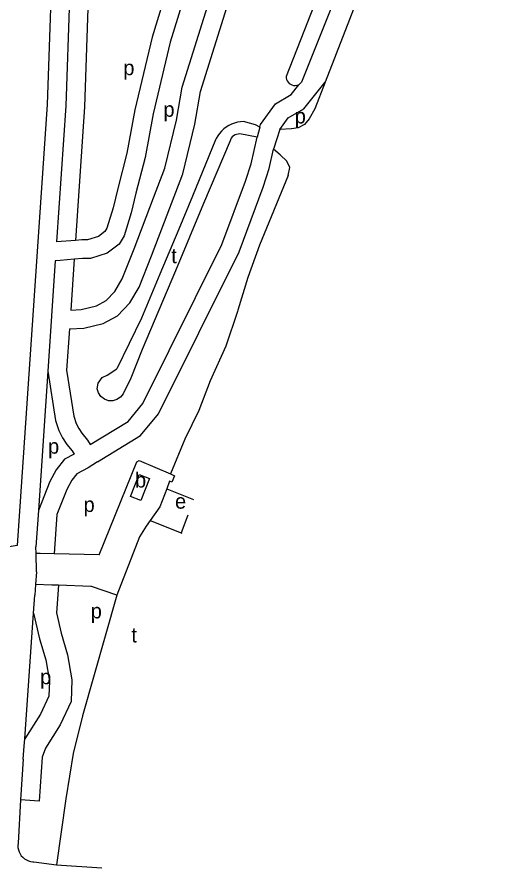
# Model space of a CAD drawing. Extents: x 157794 to 159375, y 380877 to 382306.
# Drawn here: x 159022.3 to 159149.4, y 381333.4 to 381561.1 of the extents above; entities that cross this region are included whole.
import ezdxf

# ---------------------------------------------------------------- set-up
doc = ezdxf.new("R2010")
doc.units = 0
for name, color, linetype in [('BLT_Basislijn', 7, 'Continuous'), ('BLT_Bebouwing', 7, 'Continuous'), ('BLT_Centroide', 7, 'Continuous')]:
    doc.layers.add(name, color=color, linetype=linetype)

msp = doc.modelspace()

# ---------------------------------------------------------------- linework, layer by layer
at = {"layer": 'BLT_Basislijn'}
for p, q in [((159031.37, 381565.99), (159030.38, 381537.62)), ((159036.37, 381566.07), (159035.37, 381537.28)), ((159041.37, 381566.09), (159040.37, 381537.03)), ((159097.74, 381542.91), (159098.42, 381543.64)), ((159104.74, 381543.62), (159102.01, 381536.5)), ((159030.38, 381537.62), (159022.42, 381419.62)), ((159035.37, 381537.28), (159032.92, 381500.89)), ((159040.37, 381537.03), (159037.95, 381501.27)), ((159087.26, 381531.61), (159086.59, 381528.93)), ((159092.64, 381530.94), (159090.97, 381525.68)), ((159086.59, 381528.93), (159081.96, 381529.76)), ((159079.32, 381527.95), (159072.2, 381511.17)), ((159072.2, 381511.17), (159064.69, 381493.16)), ((159065.6, 381504.32), (159060.54, 381492.28)), ((159037.95, 381501.27), (159032.92, 381500.89)), ((159039.65, 381501.4), (159037.95, 381501.27)), ((159032.58, 381495.85), (159030.58, 381466.3)), ((159033.87, 381495.95), (159032.58, 381495.85)), ((159037.61, 381496.23), (159033.87, 381495.95)), ((159037.61, 381496.23), (159036.7, 381482.64)), ((159060.54, 381492.28), (159055.66, 381480.47)), ((159064.69, 381493.16), (159055.78, 381472.1)), ((159055.66, 381480.47), (159049.01, 381466.95)), ((159036.36, 381477.61), (159035.61, 381466.52)), ((159030.58, 381466.3), (159028.07, 381429.01)), ((159063.36, 381438.8), (159064.49, 381438.32)), ((159062.37, 381434.85), (159069.53, 381431.96)), ((159028.07, 381429.01), (159027.41, 381419.28)), ((159033, 381427.91), (159032.29, 381417.41)), ((159057.92, 381426.33), (159066.24, 381423.03)), ((159068.06, 381427.76), (159066.24, 381423.03)), ((159055.07, 381421.97), (159049.06, 381406.33)), ((159066.24, 381423.03), (159066.38, 381422.97)), ((159022.42, 381419.62), (159011.92, 381417.93)), ((159027.44, 381417.53), (159027.41, 381419.28)), ((159027.54, 381412.62), (159027.44, 381417.53)), ((159028.49, 381417.51), (159027.44, 381417.53)), ((159032.29, 381417.41), (159028.49, 381417.51)), ((159044.27, 381417.12), (159032.29, 381417.41)), ((159027.54, 381412.62), (159027.31, 381409.24)), ((159027.31, 381409.24), (159027.12, 381406.39)), ((159031.63, 381409.08), (159027.31, 381409.24)), ((159033.44, 381409.01), (159031.63, 381409.08)), ((159042.06, 381408.69), (159033.44, 381409.01)), ((159026.78, 381401.55), (159027.12, 381406.39)), ((159024.4, 381367.92), (159026.78, 381401.55)), ((159024.26, 381365.96), (159024.4, 381367.92)), ((159024.01, 381362.48), (159024.26, 381365.96)), ((159024.01, 381362.48), (159023.26, 381351.59)), ((159023.26, 381351.59), (159022.6, 381339.99)), ((159026.6, 381335.02), (159026.79, 381334.99)), ((159026.79, 381334.99), (159032.89, 381334.17)), ((159032.89, 381334.17), (159045.02, 381333.37))]:
    msp.add_line(p, q, dxfattribs=at)
for points in [[(159149.36, 381672.32), (159141.87, 381652.41), (159100, 381547.62), (159098.42, 381543.64)], [(159036.36, 381477.61), (159040.23, 381477.84), (159045.36, 381479.09), (159049.18, 381481.13), (159052.52, 381484.54), (159054.98, 381488.78), (159058.34, 381497.19), (159066.67, 381519.12), (159069.91, 381532.4), (159071.39, 381541.15), (159080.3, 381569.64), (159085.12, 381578.02), (159089.78, 381584.29), (159098.44, 381594.27), (159112.17, 381608.95)], [(159127.48, 381601.4), (159114.23, 381568.04), (159104.74, 381543.62)], [(159113.39, 381593.87), (159100, 381559.65), (159094.31, 381545.18)], [(159065.13, 381575), (159062.85, 381569.99), (159058.49, 381555.65), (159053.86, 381536.2), (159051.72, 381524.58), (159049.29, 381515.13), (159048.08, 381509.99), (159046.35, 381504.53), (159045.84, 381503.67), (159044.1, 381502.37), (159041.2, 381501.4), (159039.65, 381501.4)], [(159069.55, 381572.64), (159067.54, 381568.22), (159063.32, 381554.35), (159058.76, 381535.17), (159056.61, 381523.5), (159054.14, 381513.94), (159052.9, 381508.66), (159050.95, 381502.47), (159049.62, 381500.26), (159046.46, 381497.89), (159042.01, 381496.4), (159039.86, 381496.4), (159037.61, 381496.23)], [(159036.7, 381482.64), (159039.49, 381482.81), (159043.56, 381483.8), (159046.14, 381485.18), (159048.51, 381487.6), (159050.47, 381490.97), (159053.68, 381499.01), (159058.85, 381512.64), (159061.88, 381520.61), (159065.01, 381533.42), (159066.52, 381542.32), (159069.42, 381551.61), (159072.27, 381560.74), (159075.04, 381569.57)], [(159094.31, 381545.18), (159094.32, 381544.76), (159094.42, 381544.34), (159094.59, 381543.95), (159094.83, 381543.59), (159095.13, 381543.29), (159095.48, 381543.04), (159095.87, 381542.87), (159096.29, 381542.77), (159096.72, 381542.75), (159097.14, 381542.81), (159097.74, 381542.91)], [(159087.26, 381531.61), (159087.44, 381532.26), (159091.43, 381537.86), (159095.68, 381540.36), (159097.74, 381542.91)], [(159092.64, 381530.94), (159094.89, 381534.09), (159099, 381536.52), (159104.74, 381543.62)], [(159102.01, 381536.5), (159100.44, 381533.8), (159099.21, 381532.26), (159097.53, 381531.42), (159095.76, 381531.11), (159092.64, 381530.94)], [(159082.89, 381533.11), (159082.08, 381533.05), (159081.27, 381532.91), (159080.48, 381532.69), (159079.71, 381532.4), (159078.98, 381532.03), (159078.29, 381531.59), (159077.64, 381531.09), (159077.04, 381530.53), (159076.5, 381529.91), (159076.03, 381529.24), (159075.62, 381528.53), (159075.46, 381528.19)], [(159087.26, 381531.61), (159086.14, 381532.23), (159082.89, 381533.11)], [(159041.89, 381446.64), (159052.05, 381452.87), (159055.98, 381457.63), (159077.14, 381500.17), (159083.45, 381517.16), (159084.93, 381521.81), (159086.59, 381528.93)], [(159081.96, 381529.76), (159081.51, 381529.75), (159081.06, 381529.66), (159080.64, 381529.5), (159080.25, 381529.27), (159079.92, 381528.97), (159079.63, 381528.61), (159079.42, 381528.22), (159079.32, 381527.95)], [(159075.46, 381528.19), (159069.27, 381513.08), (159065.6, 381504.32)], [(159043.89, 381442), (159055.38, 381449.04), (159060.2, 381454.89), (159081.74, 381498.18), (159088.18, 381515.52), (159089.76, 381520.48), (159090.97, 381525.68)], [(159094.84, 381518.61), (159095.3, 381520.83), (159094.46, 381522.52), (159092.69, 381524.21), (159090.97, 381525.68)], [(159094.84, 381518.61), (159087.19, 381500), (159084.1, 381491.35), (159081.38, 381482.58), (159081.29, 381482.28)], [(159081.29, 381482.28), (159078.21, 381472.96), (159074.02, 381463.74), (159070.93, 381455.77), (159067.2, 381448.08), (159063.36, 381438.8)], [(159055.78, 381472.1), (159052.78, 381464.4), (159050.74, 381460.26), (159050, 381459.32), (159049.05, 381458.68), (159047.92, 381458.36), (159046.77, 381458.4), (159045.72, 381458.77), (159044.75, 381459.52), (159044.1, 381460.49), (159043.78, 381461.61), (159044.02, 381463.08), (159045.13, 381464.61), (159046.48, 381465.26), (159049.01, 381466.95)], [(159030.58, 381466.3), (159032.62, 381453.08), (159033.54, 381450.39), (159034.48, 381448.49), (159035.62, 381446.68), (159037.1, 381444.98), (159037.58, 381444.11), (159035.05, 381442.77), (159032.78, 381439.89), (159031.09, 381436.78), (159028.07, 381429.01)], [(159035.61, 381466.52), (159037.49, 381454.28), (159038.17, 381452.31), (159038.85, 381450.94), (159039.65, 381449.67), (159041.23, 381447.85), (159041.89, 381446.64)], [(159044.27, 381417.12), (159054.39, 381442.07), (159054.96, 381442.39), (159063.36, 381438.8)], [(159043.89, 381442), (159041.36, 381440.46), (159038.32, 381438.84), (159036.97, 381437.13), (159035.64, 381434.67), (159033, 381427.91)], [(159064.49, 381438.32), (159063.77, 381436.62), (159063.13, 381436.87), (159062.37, 381434.85)], [(159062.37, 381434.85), (159060.52, 381429.98), (159057.92, 381426.33)], [(159057.92, 381426.33), (159056.86, 381424.83), (159055.07, 381421.97)], [(159033.44, 381409.01), (159032.92, 381401.6), (159034.13, 381396.2), (159035.86, 381390.4), (159037, 381383.75), (159036.82, 381377.95), (159033.89, 381371.66), (159029.92, 381365.43), (159029.07, 381363.06)], [(159049.06, 381406.33), (159042.23, 381408.71), (159042.06, 381408.69)], [(159049.06, 381406.33), (159039.83, 381374.04), (159037.35, 381364.03)], [(159026.78, 381401.55), (159028.32, 381394.68), (159030.01, 381389.03), (159030.98, 381383.33), (159030.86, 381379.37), (159028.62, 381374.55), (159024.4, 381367.92)], [(159029.07, 381363.06), (159028.25, 381351.25), (159023.26, 381351.59)], [(159037.35, 381364.03), (159035.4, 381351.91), (159032.89, 381334.17)], [(159022.6, 381339.99), (159022.55, 381339.41), (159022.59, 381338.82), (159022.7, 381338.24), (159022.89, 381337.68), (159023.15, 381337.15), (159023.49, 381336.66), (159023.89, 381336.23), (159024.34, 381335.85), (159024.84, 381335.53), (159025.37, 381335.29), (159025.94, 381335.11), (159026.6, 381335.02)]]:
    msp.add_lwpolyline(points, dxfattribs=at)
at = {"layer": 'BLT_Bebouwing'}
msp.add_lwpolyline([(159055, 381438.63), (159057.77, 381437.54), (159055.47, 381431.68), (159052.7, 381432.77), (159055, 381438.63)], dxfattribs=at)

# ---------------------------------------------------------------- texts
at = {"layer": 'BLT_Centroide'}
for s, p in [('p', (159050.77, 381545.49)), ('p', (159061.49, 381534.36)), ('p', (159096.61, 381532.57)), ('t', (159063.58, 381495.18)), ('p', (159030.64, 381444.22)), ('b', (159053.9, 381435.16)), ('p', (159040.14, 381428.62)), ('e', (159064.6, 381429.5)), ('p', (159042.05, 381400.15)), ('t', (159052.91, 381393.72)), ('p', (159028.52, 381382.53))]:
    msp.add_text(s, height=4, dxfattribs=at).set_placement(p)

doc.saveas('drawing.dxf')
